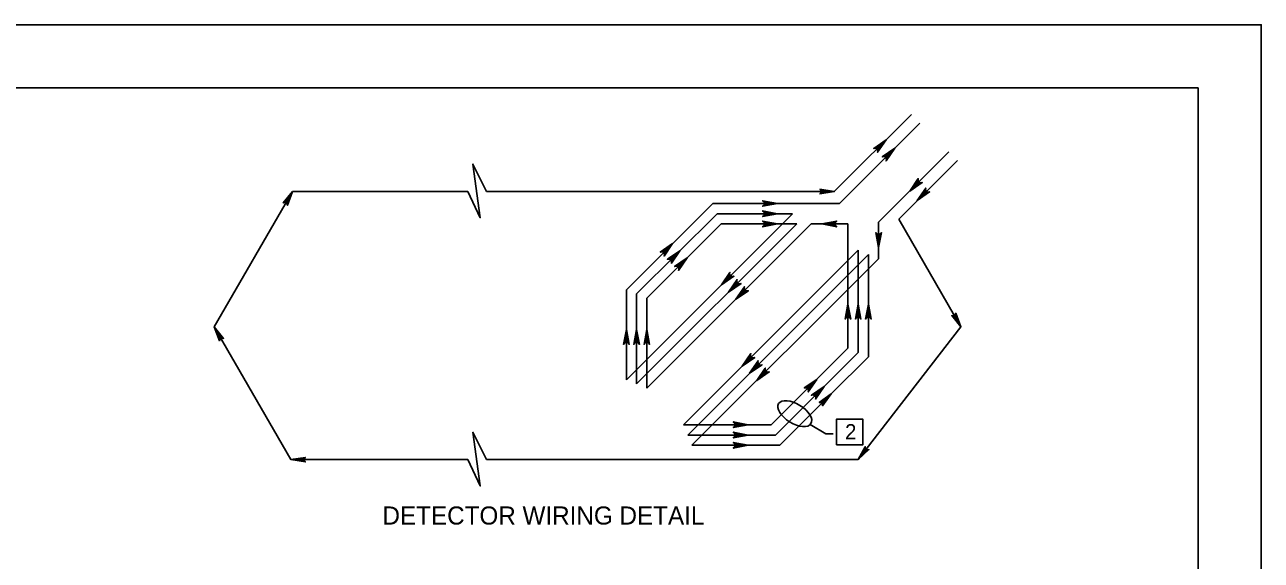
# Model space of a CAD drawing. Extents: x 2709 to 3899, y 22 to 1210.
# Drawn here: x 3256.6 to 3549.9, y 1083 to 1210.2 of the extents above; entities that cross this region are included whole.
import ezdxf

# ---------------------------------------------------------------- set-up
doc = ezdxf.new("R2010")
doc.units = 0
for name, color, linetype in [('1', 7, 'Continuous'), ('15', 7, 'Continuous'), ('16', 7, 'Continuous'), ('17', 7, 'Continuous'), ('PLT-BNDY', 7, 'Continuous')]:
    doc.layers.add(name, color=color, linetype=linetype)

msp = doc.modelspace()

# ---------------------------------------------------------------- linework, layer by layer
at = {"layer": '1'}
for p in [(2748.86, 1195.17), (3534.86, 631.17)]:
    msp.add_line(p, (3534.86, 1195.17), dxfattribs=at)
for points in [[(3318.1, 1167.92), (3318.37, 1167.91), (3320.09, 1170.55), (3318.1, 1167.92), (3317.89, 1167.85), (3320.09, 1170.55), (3318.65, 1167.75), (3318.8, 1167.53), (3320.09, 1170.55), (3318.85, 1167.3), (3318.8, 1167.53)], [(3445.31, 1170.96), (3445.44, 1170.72), (3448.58, 1170.55), (3445.31, 1170.96), (3445.15, 1171.1), (3448.58, 1170.55), (3445.44, 1170.39), (3445.32, 1170.16), (3448.58, 1170.55), (3445.15, 1170), (3445.32, 1170.16)], [(3477.34, 1141.42), (3477.19, 1141.19), (3478.62, 1138.38), (3477.34, 1141.42), (3477.38, 1141.63), (3478.62, 1138.38), (3476.91, 1141.03), (3476.65, 1141.01), (3478.62, 1138.38), (3476.43, 1141.08), (3476.65, 1141.01)], [(3302.8, 1135.34), (3302.94, 1135.57), (3301.52, 1138.38), (3302.8, 1135.34), (3302.76, 1135.13), (3301.52, 1138.38), (3303.23, 1135.73), (3303.49, 1135.75), (3301.52, 1138.38), (3303.71, 1135.68), (3303.49, 1135.75)], [(3445.25, 1120.48), (3445.5, 1120.4), (3447.85, 1122.51), (3445.25, 1120.48), (3445.03, 1120.47), (3447.85, 1122.51), (3445.74, 1120.17), (3445.82, 1119.93), (3447.85, 1122.51), (3445.81, 1119.69), (3445.82, 1119.93)], [(3456.57, 1109.21), (3456.31, 1109.26), (3454.24, 1106.88), (3456.57, 1109.21), (3456.78, 1109.26), (3454.24, 1106.88), (3456.04, 1109.46), (3455.93, 1109.7), (3454.24, 1106.88), (3455.91, 1109.93), (3455.93, 1109.7)], [(3322.98, 1106.47), (3322.85, 1106.7), (3319.71, 1106.88), (3322.98, 1106.47), (3323.14, 1106.32), (3319.71, 1106.88), (3322.85, 1107.03), (3322.97, 1107.27), (3319.71, 1106.88), (3323.14, 1107.42), (3322.97, 1107.27)]]:
    msp.add_lwpolyline(points, dxfattribs=at)
at = {"layer": '15'}
msp.add_lwpolyline([(3449.14, 1110.38), (3455.31, 1110.38), (3455.31, 1116.52), (3449.14, 1116.52)], close=True, dxfattribs=at)
at = {"layer": '16'}
for p, q in [((3466.87, 1188.84), (3448.58, 1170.55)), ((3468.9, 1186.8), (3449.81, 1167.71)), ((3475.76, 1179.94), (3459.1, 1163.28)), ((3477.8, 1177.91), (3463.85, 1163.96)), ((3320.09, 1170.55), (3301.52, 1138.38)), ((3361.64, 1170.55), (3320.09, 1170.55)), ((3448.58, 1170.55), (3366.06, 1170.55)), ((3419.75, 1167.71), (3399.27, 1147.23)), ((3449.81, 1167.71), (3419.75, 1167.71)), ((3438.69, 1165.29), (3399.27, 1125.86)), ((3420.76, 1165.29), (3401.69, 1146.22)), ((3438.69, 1165.29), (3420.76, 1165.29)), ((3439.69, 1162.86), (3401.69, 1124.86)), ((3421.76, 1162.86), (3404.12, 1145.22)), ((3443.12, 1162.86), (3404.12, 1123.85)), ((3439.69, 1162.86), (3421.76, 1162.86)), ((3451.82, 1162.86), (3443.12, 1162.86)), ((3451.82, 1133.34), (3451.82, 1162.86)), ((3459.1, 1154.58), (3459.1, 1163.28)), ((3478.62, 1138.38), (3463.85, 1163.96)), ((3454.25, 1156.59), (3412.81, 1115.16)), ((3454.25, 1132.33), (3454.25, 1156.59)), ((3456.67, 1155.58), (3413.82, 1112.73)), ((3459.1, 1154.58), (3414.82, 1110.3)), ((3456.67, 1131.33), (3456.67, 1155.58)), ((3399.27, 1125.86), (3399.27, 1147.23)), ((3401.69, 1124.86), (3401.69, 1146.22)), ((3404.12, 1123.85), (3404.12, 1145.22)), ((3301.52, 1138.38), (3319.71, 1106.88)), ((3454.24, 1106.88), (3478.62, 1138.38)), ((3451.82, 1133.34), (3433.64, 1115.16)), ((3454.25, 1132.33), (3434.65, 1112.73)), ((3456.67, 1131.33), (3447.85, 1122.51)), ((3447.85, 1122.51), (3435.65, 1110.3)), ((3433.64, 1115.16), (3412.81, 1115.16)), ((3434.65, 1112.73), (3413.82, 1112.73)), ((3435.65, 1110.3), (3414.82, 1110.3)), ((3319.71, 1106.88), (3361.64, 1106.88)), ((3366.06, 1106.88), (3454.24, 1106.88))]:
    msp.add_line(p, q, dxfattribs=at)
for points in [[(3460.89, 1182.83), (3457.92, 1180.8), (3458.25, 1180.86), (3460.89, 1182.83), (3458.51, 1180.79), (3458.71, 1180.65), (3460.89, 1182.83), (3458.85, 1180.45), (3458.92, 1180.19), (3460.89, 1182.83), (3458.86, 1179.86), (3458.92, 1180.19), (3458.85, 1180.45), (3458.71, 1180.65), (3458.51, 1180.79), (3458.25, 1180.86)], [(3462.91, 1180.81), (3459.94, 1178.78), (3460.27, 1178.84), (3462.91, 1180.81), (3460.53, 1178.77), (3460.73, 1178.63), (3462.91, 1180.81), (3460.87, 1178.43), (3460.94, 1178.17), (3462.91, 1180.81), (3460.88, 1177.84), (3460.94, 1178.17), (3460.87, 1178.43), (3460.73, 1178.63), (3460.53, 1178.77), (3460.27, 1178.84)], [(3366.06, 1170.55), (3362.87, 1177.06), (3364.61, 1164.32), (3361.64, 1170.55)], [(3466.48, 1170.65), (3469.44, 1172.68), (3469.12, 1172.62), (3466.48, 1170.65), (3468.85, 1172.69), (3468.65, 1172.83), (3466.48, 1170.65), (3468.51, 1173.03), (3468.45, 1173.29), (3466.48, 1170.65), (3468.5, 1173.62), (3468.45, 1173.29), (3468.51, 1173.03), (3468.65, 1172.83), (3468.85, 1172.69), (3469.12, 1172.62)], [(3468.23, 1168.41), (3471.19, 1170.44), (3470.87, 1170.38), (3468.23, 1168.41), (3470.6, 1170.45), (3470.4, 1170.59), (3468.23, 1168.41), (3470.26, 1170.78), (3470.2, 1171.05), (3468.23, 1168.41), (3470.26, 1171.37), (3470.2, 1171.05), (3470.26, 1170.78), (3470.4, 1170.59), (3470.6, 1170.45), (3470.87, 1170.38)], [(3435.11, 1167.71), (3431.58, 1168.37), (3431.85, 1168.19), (3435.11, 1167.71), (3431.99, 1167.95), (3432.03, 1167.71), (3435.11, 1167.71), (3431.99, 1167.48), (3431.85, 1167.24), (3435.11, 1167.71), (3431.58, 1167.05), (3431.85, 1167.24), (3431.99, 1167.48), (3432.03, 1167.71), (3431.99, 1167.95), (3431.85, 1168.19)], [(3435.11, 1165.29), (3431.58, 1165.95), (3431.85, 1165.76), (3435.11, 1165.29), (3431.99, 1165.52), (3432.03, 1165.29), (3435.11, 1165.29), (3431.99, 1165.05), (3431.85, 1164.81), (3435.11, 1165.29), (3431.58, 1164.62), (3431.85, 1164.81), (3431.99, 1165.05), (3432.03, 1165.29), (3431.99, 1165.52), (3431.85, 1165.76)], [(3435.11, 1162.86), (3431.58, 1163.52), (3431.85, 1163.33), (3435.11, 1162.86), (3431.99, 1163.1), (3432.03, 1162.86), (3435.11, 1162.86), (3431.99, 1162.62), (3431.85, 1162.39), (3435.11, 1162.86), (3431.58, 1162.2), (3431.85, 1162.39), (3431.99, 1162.62), (3432.03, 1162.86), (3431.99, 1163.1), (3431.85, 1163.33)], [(3445.64, 1162.86), (3449.17, 1162.2), (3448.9, 1162.39), (3445.64, 1162.86), (3448.76, 1162.62), (3448.72, 1162.86), (3445.64, 1162.86), (3448.76, 1163.1), (3448.9, 1163.33), (3445.64, 1162.86), (3449.17, 1163.52), (3448.9, 1163.33), (3448.76, 1163.1), (3448.72, 1162.86), (3448.76, 1162.62), (3448.9, 1162.39)], [(3459.1, 1157.29), (3459.76, 1160.82), (3459.57, 1160.55), (3459.1, 1157.29), (3459.34, 1160.41), (3459.1, 1160.37), (3459.1, 1157.29), (3458.86, 1160.41), (3458.63, 1160.55), (3459.1, 1157.29), (3458.44, 1160.82), (3458.63, 1160.55), (3458.86, 1160.41), (3459.1, 1160.37), (3459.34, 1160.41), (3459.57, 1160.55)], [(3410.24, 1158.2), (3407.28, 1156.17), (3407.6, 1156.23), (3410.24, 1158.2), (3407.87, 1156.17), (3408.07, 1156.03), (3410.24, 1158.2), (3408.2, 1155.83), (3408.27, 1155.56), (3410.24, 1158.2), (3408.21, 1155.24), (3408.27, 1155.56), (3408.2, 1155.83), (3408.07, 1156.03), (3407.87, 1156.17), (3407.6, 1156.23)], [(3411.96, 1156.49), (3408.99, 1154.46), (3409.32, 1154.52), (3411.96, 1156.49), (3409.58, 1154.45), (3409.78, 1154.31), (3411.96, 1156.49), (3409.92, 1154.12), (3409.99, 1153.85), (3411.96, 1156.49), (3409.93, 1153.52), (3409.99, 1153.85), (3409.92, 1154.12), (3409.78, 1154.31), (3409.58, 1154.45), (3409.32, 1154.52)], [(3413.67, 1154.77), (3410.71, 1152.74), (3411.03, 1152.8), (3413.67, 1154.77), (3411.3, 1152.74), (3411.5, 1152.6), (3413.67, 1154.77), (3411.63, 1152.4), (3411.7, 1152.13), (3413.67, 1154.77), (3411.64, 1151.81), (3411.7, 1152.13), (3411.63, 1152.4), (3411.5, 1152.6), (3411.3, 1152.74), (3411.03, 1152.8)], [(3421.79, 1148.39), (3424.76, 1150.42), (3424.43, 1150.36), (3421.79, 1148.39), (3424.17, 1150.43), (3423.97, 1150.57), (3421.79, 1148.39), (3423.83, 1150.76), (3423.76, 1151.03), (3421.79, 1148.39), (3423.82, 1151.36), (3423.76, 1151.03), (3423.83, 1150.76), (3423.97, 1150.57), (3424.17, 1150.43), (3424.43, 1150.36)], [(3423.51, 1146.67), (3426.47, 1148.7), (3426.15, 1148.64), (3423.51, 1146.67), (3425.88, 1148.71), (3425.68, 1148.85), (3423.51, 1146.67), (3425.55, 1149.05), (3425.48, 1149.31), (3423.51, 1146.67), (3425.54, 1149.64), (3425.48, 1149.31), (3425.55, 1149.05), (3425.68, 1148.85), (3425.88, 1148.71), (3426.15, 1148.64)], [(3425.22, 1144.96), (3428.19, 1146.99), (3427.86, 1146.93), (3425.22, 1144.96), (3427.6, 1147), (3427.4, 1147.14), (3425.22, 1144.96), (3427.26, 1147.33), (3427.19, 1147.6), (3425.22, 1144.96), (3427.25, 1147.93), (3427.19, 1147.6), (3427.26, 1147.33), (3427.4, 1147.14), (3427.6, 1147), (3427.86, 1146.93)], [(3451.82, 1143.79), (3451.16, 1140.26), (3451.35, 1140.53), (3451.82, 1143.79), (3451.59, 1140.67), (3451.82, 1140.71), (3451.82, 1143.79), (3452.06, 1140.67), (3452.3, 1140.53), (3451.82, 1143.79), (3452.48, 1140.26), (3452.3, 1140.53), (3452.06, 1140.67), (3451.82, 1140.71), (3451.59, 1140.67), (3451.35, 1140.53)], [(3454.25, 1143.79), (3453.59, 1140.26), (3453.77, 1140.53), (3454.25, 1143.79), (3454.01, 1140.67), (3454.25, 1140.71), (3454.25, 1143.79), (3454.48, 1140.67), (3454.72, 1140.53), (3454.25, 1143.79), (3454.91, 1140.26), (3454.72, 1140.53), (3454.48, 1140.67), (3454.25, 1140.71), (3454.01, 1140.67), (3453.77, 1140.53)], [(3456.67, 1143.79), (3456.01, 1140.26), (3456.2, 1140.53), (3456.67, 1143.79), (3456.44, 1140.67), (3456.67, 1140.71), (3456.67, 1143.79), (3456.91, 1140.67), (3457.15, 1140.53), (3456.67, 1143.79), (3457.34, 1140.26), (3457.15, 1140.53), (3456.91, 1140.67), (3456.67, 1140.71), (3456.44, 1140.67), (3456.2, 1140.53)], [(3399.27, 1137.79), (3398.6, 1134.26), (3398.79, 1134.53), (3399.27, 1137.79), (3399.03, 1134.67), (3399.27, 1134.71), (3399.27, 1137.79), (3399.5, 1134.67), (3399.74, 1134.53), (3399.27, 1137.79), (3399.93, 1134.26), (3399.74, 1134.53), (3399.5, 1134.67), (3399.27, 1134.71), (3399.03, 1134.67), (3398.79, 1134.53)], [(3401.69, 1137.79), (3401.03, 1134.26), (3401.22, 1134.53), (3401.69, 1137.79), (3401.45, 1134.67), (3401.69, 1134.71), (3401.69, 1137.79), (3401.93, 1134.67), (3402.16, 1134.53), (3401.69, 1137.79), (3402.35, 1134.26), (3402.16, 1134.53), (3401.93, 1134.67), (3401.69, 1134.71), (3401.45, 1134.67), (3401.22, 1134.53)], [(3404.12, 1137.79), (3403.45, 1134.26), (3403.64, 1134.53), (3404.12, 1137.79), (3403.88, 1134.67), (3404.12, 1134.71), (3404.12, 1137.79), (3404.35, 1134.67), (3404.59, 1134.53), (3404.12, 1137.79), (3404.78, 1134.26), (3404.59, 1134.53), (3404.35, 1134.67), (3404.12, 1134.71), (3403.88, 1134.67), (3403.64, 1134.53)], [(3426.76, 1129.1), (3429.72, 1131.13), (3429.4, 1131.07), (3426.76, 1129.1), (3429.13, 1131.14), (3428.93, 1131.27), (3426.76, 1129.1), (3428.8, 1131.47), (3428.73, 1131.74), (3426.76, 1129.1), (3428.79, 1132.06), (3428.73, 1131.74), (3428.8, 1131.47), (3428.93, 1131.27), (3429.13, 1131.14), (3429.4, 1131.07)], [(3428.47, 1127.38), (3431.44, 1129.41), (3431.11, 1129.35), (3428.47, 1127.38), (3430.85, 1129.42), (3430.65, 1129.56), (3428.47, 1127.38), (3430.51, 1129.76), (3430.44, 1130.02), (3428.47, 1127.38), (3430.5, 1130.35), (3430.44, 1130.02), (3430.51, 1129.76), (3430.65, 1129.56), (3430.85, 1129.42), (3431.11, 1129.35)], [(3430.19, 1125.67), (3433.15, 1127.7), (3432.83, 1127.64), (3430.19, 1125.67), (3432.56, 1127.71), (3432.36, 1127.84), (3430.19, 1125.67), (3432.23, 1128.04), (3432.16, 1128.31), (3430.19, 1125.67), (3432.22, 1128.63), (3432.16, 1128.31), (3432.23, 1128.04), (3432.36, 1127.84), (3432.56, 1127.71), (3432.83, 1127.64)], [(3444.42, 1125.94), (3441.46, 1123.91), (3441.78, 1123.97), (3444.42, 1125.94), (3442.05, 1123.9), (3442.25, 1123.76), (3444.42, 1125.94), (3442.38, 1123.56), (3442.45, 1123.3), (3444.42, 1125.94), (3442.39, 1122.97), (3442.45, 1123.3), (3442.38, 1123.56), (3442.25, 1123.76), (3442.05, 1123.9), (3441.78, 1123.97)], [(3446.14, 1124.22), (3443.17, 1122.19), (3443.5, 1122.25), (3446.14, 1124.22), (3443.76, 1122.18), (3443.96, 1122.04), (3446.14, 1124.22), (3444.1, 1121.85), (3444.17, 1121.58), (3446.14, 1124.22), (3444.11, 1121.25), (3444.17, 1121.58), (3444.1, 1121.85), (3443.96, 1122.04), (3443.76, 1122.18), (3443.5, 1122.25)], [(3428.13, 1115.16), (3424.6, 1115.82), (3424.87, 1115.63), (3428.13, 1115.16), (3425.01, 1115.39), (3425.05, 1115.16), (3428.13, 1115.16), (3425.01, 1114.92), (3424.87, 1114.68), (3428.13, 1115.16), (3424.6, 1114.49), (3424.87, 1114.68), (3425.01, 1114.92), (3425.05, 1115.16), (3425.01, 1115.39), (3424.87, 1115.63)], [(3366.06, 1106.88), (3362.87, 1113.39), (3364.61, 1100.65), (3361.64, 1106.88)], [(3428.13, 1112.73), (3424.6, 1113.39), (3424.87, 1113.2), (3428.13, 1112.73), (3425.01, 1112.97), (3425.05, 1112.73), (3428.13, 1112.73), (3425.01, 1112.49), (3424.87, 1112.26), (3428.13, 1112.73), (3424.6, 1112.07), (3424.87, 1112.26), (3425.01, 1112.49), (3425.05, 1112.73), (3425.01, 1112.97), (3424.87, 1113.2)], [(3428.13, 1110.3), (3424.6, 1110.97), (3424.87, 1110.78), (3428.13, 1110.3), (3425.01, 1110.54), (3425.05, 1110.3), (3428.13, 1110.3), (3425.01, 1110.07), (3424.87, 1109.83), (3428.13, 1110.3), (3424.6, 1109.64), (3424.87, 1109.83), (3425.01, 1110.07), (3425.05, 1110.3), (3425.01, 1110.54), (3424.87, 1110.78)]]:
    msp.add_lwpolyline(points, dxfattribs=at)
at = {"layer": '17'}
msp.add_lwpolyline([(3448.28, 1113.01), (3446.59, 1113.01), (3442.89, 1115.26)], dxfattribs=at)
msp.add_ellipse((3439.21, 1117.81), major_axis=(3.83, -2.38), ratio=0.511782, dxfattribs=at)
at = {"layer": 'PLT-BNDY'}
msp.add_lwpolyline([(2708.86, 1210.17), (3549.86, 1210.17), (3549.86, 616.17), (2708.86, 616.17)], close=True, dxfattribs=at)

# ---------------------------------------------------------------- texts
at = {"layer": '1'}
msp.add_text('2', height=3.6, dxfattribs=at).set_placement((3451.14, 1111.71))
at = {"layer": '17'}
msp.add_text('DETECTOR WIRING DETAIL', height=4.3, dxfattribs=at).set_placement((3341.41, 1091.46))

doc.saveas('drawing.dxf')
